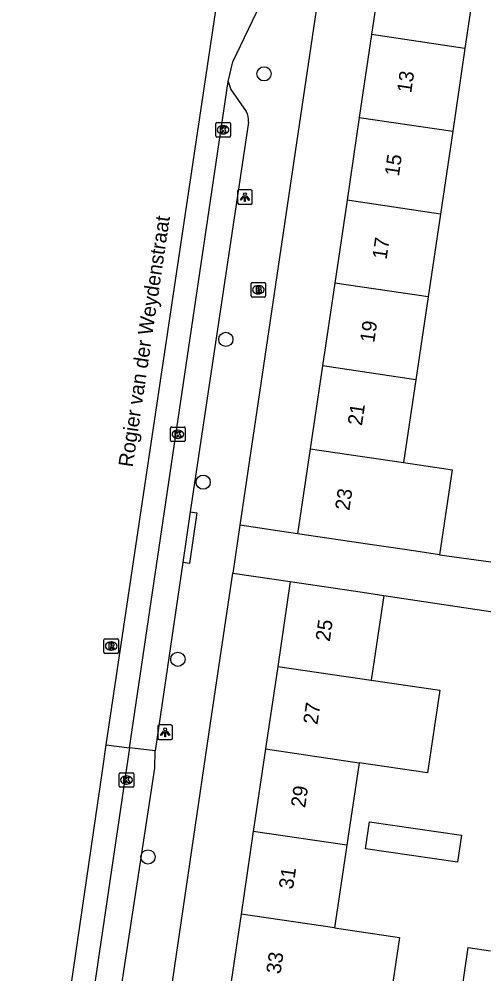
# Model space of a CAD drawing. Extents: x 163686 to 164493, y 382719 to 383870.
# Drawn here: x 163720.2 to 163752.1, y 383030.8 to 383096.3 of the extents above; entities that cross this region are included whole.
import ezdxf

# ---------------------------------------------------------------- set-up
doc = ezdxf.new("R2010")
doc.units = 0
for name, color, linetype in [('IMGEO_Boom', 7, 'Continuous'), ('IMGEO_Brandkraan', 7, 'Continuous'), ('IMGEO_Kolk', 7, 'Continuous'), ('IMGEO_Lichtpunt', 7, 'Continuous'), ('IMGEO_Openbare_ruimte_label', 7, 'Continuous'), ('IMGEO_Pand', 7, 'Continuous'), ('IMGEO_Pand_nummerreeks', 7, 'Continuous'), ('IMGEO_Parkeervlak_open', 7, 'Continuous'), ('IMGEO_Rijbaan_lokaal_open', 7, 'Continuous'), ('IMGEO_Rioolput', 7, 'Continuous'), ('IMGEO_Voetpad_open', 7, 'Continuous')]:
    doc.layers.add(name, color=color, linetype=linetype)

msp = doc.modelspace()

# ---------------------------------------------------------------- linework, layer by layer
at = {"layer": 'IMGEO_Boom'}
for centre in [(163737.044, 383092.518), (163734.421, 383074.294), (163732.869, 383064.5), (163731.134, 383052.348), (163729.085, 383038.783)]:
    msp.add_circle(centre, 0.489, dxfattribs=at)
at = {"layer": 'IMGEO_Brandkraan'}
for p, q in [((163736.149, 383077.276), (163736.149, 383078.128)), ((163736.224, 383078.202), (163737.076, 383078.202)), ((163737.15, 383078.128), (163737.15, 383077.276)), ((163736.66, 383077.422), (163736.635, 383077.422)), ((163736.637, 383077.982), (163736.662, 383077.982)), ((163737.076, 383077.202), (163736.224, 383077.202))]:
    msp.add_line(p, q, dxfattribs=at)
for points in [[(163736.149, 383077.276), (163736.149, 383078.128)], [(163736.224, 383078.202), (163737.076, 383078.202)], [(163737.15, 383078.128), (163737.15, 383077.276)], [(163736.497, 383077.902), (163736.497, 383077.502), (163736.71, 383077.502)], [(163736.728, 383077.902), (163736.497, 383077.902)], [(163736.676, 383077.821), (163736.622, 383077.821), (163736.622, 383077.745)], [(163736.622, 383077.745), (163736.675, 383077.745)], [(163736.684, 383077.669), (163736.622, 383077.669), (163736.622, 383077.588)], [(163736.622, 383077.588), (163736.684, 383077.588)], [(163737.076, 383077.202), (163736.224, 383077.202)]]:
    msp.add_lwpolyline(points, dxfattribs=at)
for centre, radius, start, end in [((163736.226, 383078.126), 0.0765, 91.55205, 178.44795), ((163736.226, 383078.126), 0.0765, 91.55205, 178.44795), ((163737.074, 383078.126), 0.0765, 1.55205, 88.44795), ((163737.074, 383078.126), 0.0765, 1.55205, 88.44795), ((163736.677, 383077.783), 0.0379, 267.82845, 90.93552), ((163736.685, 383077.628), 0.0404, 269.87594, 90.50774), ((163736.716, 383077.753), 0.251, 268.66757, 293.53466), ((163736.732, 383077.757), 0.145, 59.4692, 91.53667), ((163736.757, 383077.804), 0.0922, 285.51372, 58.15012), ((163736.762, 383077.612), 0.105, 301.31148, 78.98903), ((163736.226, 383077.278), 0.0765, 181.55205, 268.44795), ((163736.226, 383077.278), 0.0765, 181.55205, 268.44795), ((163737.074, 383077.278), 0.0765, 271.55205, 358.44795), ((163737.074, 383077.278), 0.0765, 271.55205, 358.44795)]:
    msp.add_arc(centre, radius, start, end, dxfattribs=at)
for centre, major_axis, ratio, start_param, end_param in [((163736.636, 383077.702), (-0.387, 0.002), 0.722429, 4.712389, 7.853982), ((163736.661, 383077.702), (-0.39, 0.002), 0.717154, 1.570796, 4.712389)]:
    msp.add_ellipse(centre, major_axis=major_axis, ratio=ratio, start_param=start_param, end_param=end_param, dxfattribs=at)
at = {"layer": 'IMGEO_Kolk'}
for p, q in [((163733.805, 383089.179), (163734.657, 383089.179)), ((163733.73, 383088.253), (163733.73, 383089.105)), ((163734.218, 383088.959), (163734.243, 383088.959)), ((163734.731, 383089.105), (163734.731, 383088.253)), ((163734.657, 383088.179), (163733.805, 383088.179)), ((163734.241, 383088.399), (163734.216, 383088.399)), ((163730.634, 383067.358), (163730.634, 383068.21)), ((163730.709, 383068.284), (163731.561, 383068.284)), ((163731.635, 383068.21), (163731.635, 383067.358)), ((163731.122, 383068.064), (163731.147, 383068.064)), ((163731.561, 383067.284), (163730.709, 383067.284)), ((163731.145, 383067.504), (163731.12, 383067.504)), ((163727.111, 383043.637), (163727.111, 383044.489)), ((163727.186, 383044.563), (163728.038, 383044.563)), ((163727.599, 383044.343), (163727.624, 383044.343)), ((163728.112, 383044.489), (163728.112, 383043.637)), ((163728.038, 383043.563), (163727.186, 383043.563)), ((163727.622, 383043.783), (163727.597, 383043.783))]:
    msp.add_line(p, q, dxfattribs=at)
for points in [[(163733.805, 383089.179), (163734.657, 383089.179)], [(163733.73, 383088.253), (163733.73, 383089.105)], [(163734.051, 383088.879), (163734.174, 383088.879), (163734.174, 383088.728), (163734.304, 383088.879), (163734.468, 383088.879), (163734.322, 383088.728), (163734.475, 383088.479), (163734.323, 383088.479), (163734.238, 383088.643), (163734.174, 383088.576), (163734.174, 383088.479), (163734.051, 383088.479), (163734.051, 383088.879)], [(163734.731, 383089.105), (163734.731, 383088.253)], [(163734.657, 383088.179), (163733.805, 383088.179)], [(163730.634, 383067.358), (163730.634, 383068.21)], [(163730.709, 383068.284), (163731.561, 383068.284)], [(163731.635, 383068.21), (163731.635, 383067.358)], [(163730.955, 383067.984), (163731.078, 383067.984), (163731.078, 383067.833), (163731.208, 383067.984), (163731.372, 383067.984), (163731.226, 383067.833), (163731.379, 383067.584), (163731.227, 383067.584), (163731.142, 383067.748), (163731.078, 383067.681), (163731.078, 383067.584), (163730.955, 383067.584), (163730.955, 383067.984)], [(163731.561, 383067.284), (163730.709, 383067.284)], [(163727.111, 383043.637), (163727.111, 383044.489)], [(163727.186, 383044.563), (163728.038, 383044.563)], [(163727.432, 383044.263), (163727.555, 383044.263), (163727.555, 383044.112), (163727.685, 383044.263), (163727.849, 383044.263), (163727.703, 383044.112), (163727.856, 383043.863), (163727.704, 383043.863), (163727.619, 383044.027), (163727.555, 383043.96), (163727.555, 383043.863), (163727.432, 383043.863), (163727.432, 383044.263)], [(163728.112, 383044.489), (163728.112, 383043.637)], [(163728.038, 383043.563), (163727.186, 383043.563)]]:
    msp.add_lwpolyline(points, dxfattribs=at)
for centre, start, end in [((163733.807, 383089.103), 91.55205, 178.44795), ((163733.807, 383089.103), 91.55205, 178.44795), ((163734.655, 383089.103), 1.55205, 88.44795), ((163734.655, 383089.103), 1.55205, 88.44795), ((163733.807, 383088.255), 181.55205, 268.44795), ((163733.807, 383088.255), 181.55205, 268.44795), ((163734.655, 383088.255), 271.55205, 358.44795), ((163734.655, 383088.255), 271.55205, 358.44795), ((163730.711, 383068.208), 91.55205, 178.44795), ((163730.711, 383068.208), 91.55205, 178.44795), ((163731.559, 383068.208), 1.55205, 88.44795), ((163731.559, 383068.208), 1.55205, 88.44795), ((163730.711, 383067.36), 181.55205, 268.44795), ((163730.711, 383067.36), 181.55205, 268.44795), ((163731.559, 383067.36), 271.55205, 358.44795), ((163731.559, 383067.36), 271.55205, 358.44795), ((163727.188, 383044.487), 91.55205, 178.44795), ((163727.188, 383044.487), 91.55205, 178.44795), ((163728.036, 383044.487), 1.55205, 88.44795), ((163728.036, 383044.487), 1.55205, 88.44795), ((163727.188, 383043.639), 181.55205, 268.44795), ((163727.188, 383043.639), 181.55205, 268.44795), ((163728.036, 383043.639), 271.55205, 358.44795), ((163728.036, 383043.639), 271.55205, 358.44795)]:
    msp.add_arc(centre, 0.0765, start, end, dxfattribs=at)
for centre, major_axis, ratio, start_param, end_param in [((163734.217, 383088.679), (-0.387, 0.002), 0.722429, 4.712389, 7.853982), ((163734.242, 383088.679), (-0.39, 0.002), 0.717154, 1.570796, 4.712389), ((163731.121, 383067.784), (-0.387, 0.002), 0.722429, 4.712389, 7.853982), ((163731.146, 383067.784), (-0.39, 0.002), 0.717154, 1.570796, 4.712389), ((163727.598, 383044.063), (-0.387, 0.002), 0.722429, 4.712389, 7.853982), ((163727.623, 383044.063), (-0.39, 0.002), 0.717154, 1.570796, 4.712389)]:
    msp.add_ellipse(centre, major_axis=major_axis, ratio=ratio, start_param=start_param, end_param=end_param, dxfattribs=at)
at = {"layer": 'IMGEO_Lichtpunt'}
for p, q in [((163736.134, 383084.559), (163735.326, 383084.559)), ((163736.134, 383084.559), (163735.326, 383084.559)), ((163735.232, 383084.464), (163735.232, 383083.657)), ((163735.232, 383084.464), (163735.232, 383083.657)), ((163736.228, 383083.657), (163736.228, 383084.464)), ((163736.228, 383083.657), (163736.228, 383084.464)), ((163735.326, 383083.563), (163736.134, 383083.563)), ((163735.326, 383083.563), (163736.134, 383083.563)), ((163729.765, 383047.742), (163729.765, 383046.935)), ((163729.765, 383047.742), (163729.765, 383046.935)), ((163730.667, 383047.837), (163729.859, 383047.837)), ((163730.667, 383047.837), (163729.859, 383047.837)), ((163730.761, 383046.935), (163730.761, 383047.742)), ((163730.761, 383046.935), (163730.761, 383047.742)), ((163729.859, 383046.841), (163730.667, 383046.841)), ((163729.859, 383046.841), (163730.667, 383046.841))]:
    msp.add_line(p, q, dxfattribs=at)
for points in [[(163735.606, 383084.128), (163735.645, 383084.1), (163735.457, 383083.838), (163735.419, 383083.865), (163735.606, 383084.128)], [(163735.708, 383084.08), (163735.755, 383084.08), (163735.755, 383083.758), (163735.708, 383083.758), (163735.708, 383084.08)], [(163735.818, 383084.1), (163735.856, 383084.127), (163736.043, 383083.865), (163736.004, 383083.837), (163735.818, 383084.1)], [(163730.139, 383047.406), (163730.178, 383047.378), (163729.99, 383047.116), (163729.952, 383047.143), (163730.139, 383047.406)], [(163730.241, 383047.358), (163730.288, 383047.358), (163730.288, 383047.036), (163730.241, 383047.036), (163730.241, 383047.358)], [(163730.351, 383047.378), (163730.389, 383047.405), (163730.576, 383047.143), (163730.537, 383047.115), (163730.351, 383047.378)]]:
    msp.add_lwpolyline(points, dxfattribs=at)
for centre in [(163735.731, 383084.262), (163730.264, 383047.54)]:
    msp.add_circle(centre, 0.0994, dxfattribs=at)
for centre, start, end in [((163735.326, 383084.464), 90, 180), ((163735.326, 383084.464), 90, 180), ((163736.134, 383084.464), 0, 90), ((163736.134, 383084.464), 0, 90), ((163735.326, 383083.657), 180, 270), ((163735.326, 383083.657), 180, 270), ((163736.134, 383083.657), 270, 0), ((163736.134, 383083.657), 270, 360), ((163729.859, 383047.742), 90, 180), ((163729.859, 383047.742), 90, 180), ((163730.667, 383047.742), 0, 90), ((163730.667, 383047.742), 0, 90), ((163729.859, 383046.935), 180, 270), ((163729.859, 383046.935), 180, 270), ((163730.667, 383046.935), 270, 0), ((163730.667, 383046.935), 270, 360)]:
    msp.add_arc(centre, 0.0946, start, end, dxfattribs=at)
at = {"layer": 'IMGEO_Pand'}
for points in [[(163745.255, 383100.902), (163744.413, 383095.217)], [(163751.659, 383099.95), (163750.817, 383094.265)], [(163744.413, 383095.217), (163743.571, 383089.532)], [(163750.817, 383094.265), (163744.413, 383095.217)], [(163750.817, 383094.265), (163749.975, 383088.58)], [(163743.571, 383089.532), (163742.729, 383083.847)], [(163743.571, 383089.532), (163749.975, 383088.58)], [(163749.975, 383088.58), (163749.133, 383082.895)], [(163742.729, 383083.847), (163741.887, 383078.162)], [(163749.133, 383082.895), (163742.729, 383083.847)], [(163749.133, 383082.895), (163748.291, 383077.21)], [(163741.887, 383078.162), (163741.045, 383072.477)], [(163748.291, 383077.21), (163741.887, 383078.162)], [(163748.291, 383077.21), (163747.449, 383071.525)], [(163741.045, 383072.477), (163740.203, 383066.792)], [(163747.449, 383071.525), (163741.045, 383072.477)], [(163747.449, 383071.525), (163746.607, 383065.84)], [(163740.203, 383066.792), (163739.339, 383060.955)], [(163740.203, 383066.792), (163746.607, 383065.84)], [(163746.607, 383065.84), (163749.658, 383065.386), (163749.93, 383065.346), (163749.067, 383059.515)], [(163749.067, 383059.515), (163747.439, 383059.756), (163745.743, 383060.007), (163744.286, 383060.223), (163739.339, 383060.955)], [(163738.843, 383057.677), (163737.981, 383051.861)], [(163738.843, 383057.677), (163743.79, 383056.944), (163745.255, 383056.727)], [(163745.255, 383056.727), (163744.394, 383050.914)], [(163737.981, 383051.861), (163737.142, 383046.195)], [(163737.981, 383051.861), (163744.394, 383050.914)], [(163744.394, 383050.914), (163749.089, 383050.221), (163748.253, 383044.554), (163743.555, 383045.248)], [(163737.142, 383046.195), (163736.303, 383040.528)], [(163737.142, 383046.195), (163743.555, 383045.248)], [(163743.555, 383045.248), (163742.716, 383039.581)], [(163750.577, 383040.269), (163750.303, 383038.417), (163744.001, 383039.35), (163744.275, 383041.203), (163750.577, 383040.269)], [(163736.303, 383040.528), (163735.464, 383034.863)], [(163742.716, 383039.581), (163736.303, 383040.528)], [(163742.716, 383039.581), (163741.877, 383033.916)], [(163735.464, 383034.863), (163734.619, 383029.159)], [(163741.877, 383033.916), (163735.464, 383034.863)], [(163741.877, 383033.916), (163746.328, 383033.254), (163745.483, 383027.55)], [(163754.623, 383026.408), (163750.226, 383027.029), (163751.044, 383032.563), (163752.565, 383032.338)]]:
    msp.add_lwpolyline(points, dxfattribs=at)
at = {"layer": 'IMGEO_Parkeervlak_open'}
msp.add_lwpolyline([(163729.579, 383046.053), (163727.827, 383046.277)], dxfattribs=at)
at = {"layer": 'IMGEO_Rijbaan_lokaal_open'}
for points in [[(163734.583, 383091.982), (163734.906, 383093.335), (163737.044, 383097.857), (163737.492, 383099.361), (163737.781, 383101.353)], [(163726.227, 383046.482), (163734.137, 383099.655)], [(163727.827, 383046.277), (163734.583, 383091.982)], [(163720.25, 383005.831), (163720.306, 383005.843), (163725.965, 383044.688), (163726.227, 383046.482)], [(163727.827, 383046.277), (163722.667, 383011.394)], [(163726.227, 383046.482), (163727.827, 383046.277)]]:
    msp.add_lwpolyline(points, dxfattribs=at)
at = {"layer": 'IMGEO_Rioolput'}
for p, q in [((163726.066, 383052.828), (163726.066, 383053.68)), ((163726.141, 383053.754), (163726.993, 383053.754)), ((163726.554, 383053.534), (163726.579, 383053.534)), ((163727.067, 383053.68), (163727.067, 383052.828)), ((163726.993, 383052.754), (163726.141, 383052.754)), ((163726.577, 383052.974), (163726.552, 383052.974))]:
    msp.add_line(p, q, dxfattribs=at)
for points in [[(163726.066, 383052.828), (163726.066, 383053.68)], [(163726.141, 383053.754), (163726.993, 383053.754)], [(163726.655, 383053.452), (163726.403, 383053.454), (163726.403, 383053.054)], [(163726.403, 383053.054), (163726.527, 383053.054), (163726.527, 383053.216), (163726.538, 383053.216)], [(163726.581, 383053.373), (163726.527, 383053.373), (163726.527, 383053.292)], [(163726.527, 383053.292), (163726.579, 383053.292)], [(163726.585, 383053.187), (163726.656, 383053.054), (163726.796, 383053.054), (163726.731, 383053.18)], [(163727.067, 383053.68), (163727.067, 383052.828)], [(163726.993, 383052.754), (163726.141, 383052.754)]]:
    msp.add_lwpolyline(points, dxfattribs=at)
for centre, radius, start, end in [((163726.143, 383053.678), 0.0765, 91.55205, 178.44795), ((163726.143, 383053.678), 0.0765, 91.55205, 178.44795), ((163726.537, 383053.163), 0.0533, 26.02933, 88.69889), ((163726.563, 383053.481), 0.19, 274.7715, 282.96867), ((163726.587, 383053.277), 0.0964, 77.00612, 93.18647), ((163726.601, 383053.334), 0.0378, 276.66336, 79.67722), ((163726.654, 383053.342), 0.109, 350.36119, 89.41601), ((163726.652, 383053.342), 0.112, 277.58423, 350.98172), ((163726.636, 383053.127), 0.108, 29.51342, 73.79051), ((163726.991, 383053.678), 0.0765, 1.55205, 88.44795), ((163726.991, 383053.678), 0.0765, 1.55205, 88.44795), ((163726.143, 383052.83), 0.0765, 181.55205, 268.44795), ((163726.143, 383052.83), 0.0765, 181.55205, 268.44795), ((163726.991, 383052.83), 0.0765, 271.55205, 358.44795), ((163726.991, 383052.83), 0.0765, 271.55205, 358.44795)]:
    msp.add_arc(centre, radius, start, end, dxfattribs=at)
for centre, major_axis, ratio, start_param, end_param in [((163726.553, 383053.254), (-0.387, 0.002), 0.722429, 4.712389, 7.853982), ((163726.578, 383053.254), (-0.39, 0.002), 0.717154, 1.570796, 4.712389)]:
    msp.add_ellipse(centre, major_axis=major_axis, ratio=ratio, start_param=start_param, end_param=end_param, dxfattribs=at)
at = {"layer": 'IMGEO_Voetpad_open'}
for points in [[(163744.687, 383124.374), (163735.38, 383061.541)], [(163734.583, 383091.982), (163734.767, 383091.442), (163735.812, 383089.943)], [(163735.973, 383089.21), (163731.983, 383062.472)], [(163731.983, 383062.472), (163732.44, 383062.398), (163731.927, 383058.925), (163731.479, 383058.989)], [(163731.983, 383062.472), (163731.479, 383058.989)], [(163735.38, 383061.541), (163734.894, 383058.262)], [(163739.339, 383060.955), (163735.38, 383061.541)], [(163749.067, 383059.515), (163756.957, 383058.438)], [(163731.479, 383058.989), (163729.579, 383046.053)], [(163728.194, 383012.617), (163733.393, 383048.127), (163734.894, 383058.262)], [(163734.894, 383058.262), (163738.843, 383057.677)], [(163745.255, 383056.727), (163756.214, 383055.08)], [(163724.816, 383013.89), (163729.558, 383044.867), (163729.579, 383046.053)]]:
    msp.add_lwpolyline(points, dxfattribs=at)
msp.add_arc((163734.975, 383089.375), 1.011, 350.61023, 34.16583, dxfattribs=at)

# ---------------------------------------------------------------- texts
at = {"layer": 'IMGEO_Openbare_ruimte_label'}
msp.add_text('Rogier van der Weydenstraat', height=1, rotation=81.54574, dxfattribs=at).set_placement((163728.036, 383065.49))
at = {"layer": 'IMGEO_Pand_nummerreeks'}
for s, rotation, p in [('13', 81.57534, (163747.129, 383091.164)), ('15', 81.57534, (163746.283, 383085.452)), ('17', 81.57534, (163745.437, 383079.739)), ('19', 81.57534, (163744.591, 383074.027)), ('21', 81.57773, (163743.749, 383068.337)), ('23', 81.57773, (163742.887, 383062.513)), ('25', 81.57426, (163741.544, 383053.527)), ('27', 81.572, (163740.699, 383047.823)), ('29', 81.57426, (163739.855, 383042.12)), ('31', 81.57426, (163739.026, 383036.528)), ('33', 81.572, (163738.165, 383030.712))]:
    msp.add_text(s, height=1, rotation=rotation, dxfattribs=at).set_placement(p)

doc.saveas('drawing.dxf')
